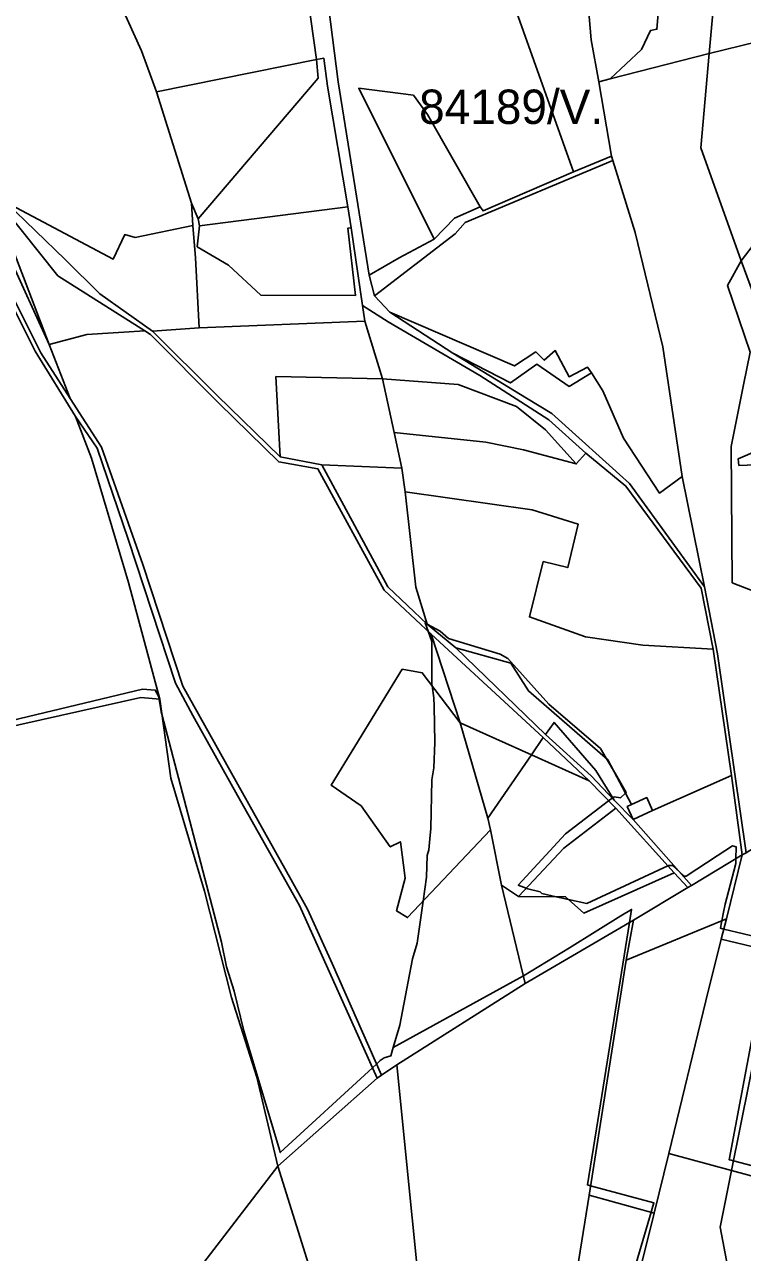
# Model space of a CAD drawing. Extents: x -477304 to -465429, y -1159113 to -1149210.
# Drawn here: x -471269 to -470956, y -1155977 to -1155441 of the extents above; entities that cross this region are included whole.
import ezdxf

# ---------------------------------------------------------------- set-up
doc = ezdxf.new("R2010")
doc.units = 0
for name, color, linetype in [('BPEJ_s', 7, 'Continuous'), ('PUPFL_s', 7, 'Continuous'), ('trav_porost_s', 7, 'Continuous')]:
    doc.layers.add(name, color=color, linetype=linetype)

msp = doc.modelspace()

# ---------------------------------------------------------------- linework, layer by layer
at = {"layer": 'BPEJ_s'}
for points in [[(-470946.75, -1155839.87), (-470963.86, -1155835.82), (-470965.36, -1155835.46), (-470964.99, -1155833.6), (-470964.71, -1155832.16), (-470963.98, -1155828.41), (-470963.32, -1155824.99), (-470961.14, -1155816.67), (-470958.64, -1155807.15), (-470958.58, -1155805.11), (-470958.43, -1155799.92), (-470960.05, -1155799.5), (-470966.71, -1155803.83), (-470980.32, -1155812.67), (-470981.17, -1155812.67), (-470983.22, -1155810.79), (-470986.26, -1155808), (-470987.96, -1155808), (-470988.29, -1155808.15), (-471023.66, -1155824.57), (-471031.62, -1155822.84), (-471037, -1155821.67), (-471043.21, -1155820.32), (-471044.06, -1155819.47), (-471049.37, -1155818.2), (-471050.04, -1155817.95), (-471052.42, -1155817.06), (-471053.59, -1155816.62), (-471033.01, -1155794.19), (-471014.12, -1155779.83), (-471012.54, -1155778.63), (-471012.33, -1155778.47), (-471011.76, -1155778.04), (-471009, -1155778.46), (-471006.75, -1155776.48), (-471006.42, -1155776.18), (-471011.18, -1155768.1), (-471015.21, -1155761.25), (-471017.71, -1155757), (-471040.23, -1155737.67), (-471058.08, -1155717.69), (-471061.48, -1155715.78), (-471084.01, -1155708.98), (-471087.62, -1155705.79), (-471093.25, -1155702.73), (-471093.74, -1155702.47), (-471094.24, -1155702.2), (-471092.9, -1155705.79), (-471091.23, -1155710.26), (-471091.23, -1155728.95), (-471091.13, -1155729.66), (-471090.38, -1155734.9), (-471090.3, -1155738.5), (-471089.95, -1155754.45), (-471090.38, -1155765.5), (-471091.23, -1155770.6), (-471091.66, -1155791.85), (-471092.07, -1155796.37), (-471092.5, -1155801.2), (-471093.35, -1155803.75), (-471093.57, -1155813.1), (-471095.03, -1155823.54), (-471096.31, -1155832.71), (-471097.6, -1155841.99), (-471099.73, -1155848.79), (-471101.63, -1155858.73), (-471105.25, -1155877.69), (-471108.14, -1155887.49), (-471109.22, -1155891.15), (-471112.05, -1155891.93), (-471113.75, -1155893.2), (-471115.36, -1155894.68)], [(-471105.25, -1155877.69), (-471101.63, -1155858.73), (-471099.73, -1155848.79), (-471097.6, -1155841.99), (-471096.31, -1155832.71), (-471095.03, -1155823.54), (-471093.57, -1155813.1), (-471093.35, -1155803.75), (-471092.5, -1155801.2), (-471092.07, -1155796.37), (-471091.66, -1155791.85), (-471091.23, -1155770.6), (-471090.38, -1155765.5), (-471089.95, -1155754.45), (-471090.3, -1155738.5), (-471090.38, -1155734.9), (-471091.13, -1155729.66), (-471091.23, -1155728.95), (-471091.23, -1155710.26), (-471092.9, -1155705.79), (-471094.24, -1155702.2), (-471093.74, -1155702.47), (-471093.25, -1155702.73), (-471087.62, -1155705.79), (-471084.01, -1155708.98), (-471061.48, -1155715.78), (-471058.08, -1155717.69), (-471040.23, -1155737.67), (-471017.71, -1155757), (-471015.21, -1155761.25), (-471011.18, -1155768.1), (-471006.42, -1155776.18), (-471006.75, -1155776.48), (-471009, -1155778.46), (-471011.76, -1155778.04), (-471012.33, -1155778.47), (-471012.54, -1155778.63), (-471014.12, -1155779.83), (-471033.01, -1155794.19), (-471053.59, -1155816.62), (-471052.42, -1155817.06), (-471050.04, -1155817.95), (-471049.37, -1155818.2), (-471044.06, -1155819.47), (-471043.21, -1155820.32), (-471037, -1155821.67), (-471031.62, -1155822.84), (-471023.66, -1155824.57), (-470988.29, -1155808.15), (-470987.96, -1155808), (-470986.26, -1155808), (-470983.22, -1155810.79), (-470981.17, -1155812.67), (-470980.32, -1155812.67), (-470966.71, -1155803.83), (-470960.05, -1155799.5), (-470958.43, -1155799.92), (-470958.58, -1155805.11), (-470958.64, -1155807.15), (-470961.14, -1155816.67), (-470963.32, -1155824.99), (-470963.98, -1155828.41), (-470964.71, -1155832.16), (-470964.99, -1155833.6), (-470965.36, -1155835.46), (-470963.86, -1155835.82), (-470946.75, -1155839.87)], [(-471115.36, -1155894.68), (-471117.11, -1155896.29), (-471157.37, -1155933.32), (-471157.74, -1155932.08), (-471173.25, -1155880.24), (-471177.5, -1155862.82), (-471180.9, -1155852.19), (-471183.02, -1155841.57), (-471209.05, -1155742.05), (-471209.32, -1155741.04), (-471209.37, -1155740.85), (-471210.28, -1155735.41), (-471210.43, -1155734.48), (-471211.92, -1155731.5), (-471217.44, -1155731.08), (-471296.48, -1155749.99)], [(-471117.11, -1155896.29), (-471157.37, -1155933.32), (-471157.74, -1155932.08), (-471173.25, -1155880.24), (-471177.5, -1155862.82), (-471180.9, -1155852.19), (-471183.02, -1155841.57), (-471209.05, -1155742.05), (-471209.32, -1155741.04), (-471209.37, -1155740.85), (-471210.28, -1155735.41), (-471210.43, -1155734.48), (-471211.92, -1155731.5), (-471217.44, -1155731.08), (-471296.48, -1155749.99)], [(-471006.54, -1155996.36), (-470995.6, -1155959.34), (-470995.11, -1155957.69), (-470994.37, -1155955.21), (-471021.99, -1155947.81), (-471023.36, -1155947.44), (-471018.83, -1155919.36), (-471004.98, -1155832.86), (-471004.08, -1155827.23), (-471008.74, -1155830.08), (-471031.12, -1155843.93), (-471051.29, -1155856.17), (-471052.86, -1155857.12), (-471108.14, -1155887.49), (-471109.22, -1155891.15), (-471112.05, -1155891.93), (-471113.75, -1155893.2), (-471115.36, -1155894.68), (-471117.11, -1155896.29)], [(-471006.54, -1155996.36), (-470995.6, -1155959.34), (-470995.11, -1155957.69), (-470994.37, -1155955.21), (-471021.99, -1155947.81), (-471023.36, -1155947.44), (-471018.83, -1155919.36), (-471004.98, -1155832.86), (-471004.08, -1155827.23), (-471008.74, -1155830.08), (-471031.12, -1155843.93), (-471051.29, -1155856.17), (-471052.86, -1155857.12), (-471108.14, -1155887.49), (-471105.25, -1155877.69)], [(-470945.89, -1155853.04), (-470961.58, -1155936.43), (-470960.66, -1155936.68), (-470959.63, -1155936.95), (-470936.97, -1155942.92)], [(-470936.97, -1155942.92), (-470959.63, -1155936.95), (-470960.66, -1155936.68), (-470961.58, -1155936.43), (-470945.89, -1155853.04)]]:
    msp.add_lwpolyline(points, dxfattribs=at)
at = {"layer": 'PUPFL_s'}
for points in [[(-470871.72, -1155069.23), (-470864.73, -1155053.8), (-470854.75, -1155056.73), (-470874.14, -1155116.56), (-470891.69, -1155151.09), (-470909.48, -1155237), (-470913.11, -1155340.83), (-470928.65, -1155443.54), (-470970.24, -1155453.73), (-470967.13, -1155420.04), (-470969.04, -1155388.49), (-470964.39, -1155378.06), (-470961.07, -1155361.45), (-470948.05, -1155328.45), (-470939.67, -1155293.89), (-470930.5, -1155258.99), (-470928.23, -1155233.59), (-470914.76, -1155194.26), (-470902.7, -1155138.01), (-470885.31, -1155112)], [(-471030.7, -1155305.54), (-471026.49, -1155250.14), (-471005.26, -1155255.11), (-470973.9, -1155258.91), (-470971.66, -1155279.02), (-470974.57, -1155299.42), (-470979.84, -1155310.96), (-470979.35, -1155352), (-470985.55, -1155416.23), (-470991.83, -1155427.38), (-470993.06, -1155443.19), (-470995.88, -1155443.78), (-470999.74, -1155451.98), (-471013.47, -1155464.79), (-471018.38, -1155466.05), (-471021.76, -1155447.82), (-471023.89, -1155422.17), (-471027.1, -1155387.89), (-471027.85, -1155373.03), (-471028.89, -1155321.57)], [(-471029.47, -1155505.45), (-471055.82, -1155431.56), (-471023.89, -1155422.17), (-471021.76, -1155447.82), (-471018.38, -1155466.05), (-471012.86, -1155498.59)], [(-470922.05, -1155441.92), (-470912.71, -1155448.67), (-470911.74, -1155457.8), (-470929.64, -1155478.08), (-470940.1, -1155497.88), (-470935.6, -1155508.15), (-470921.58, -1155526.43), (-470937.69, -1155519.96), (-470956.34, -1155544.22), (-470973.93, -1155494.85), (-470970.24, -1155453.73), (-470928.65, -1155443.54)], [(-471136.72, -1155468.07), (-471127.97, -1155520.72), (-471192.67, -1155528.9), (-471193.27, -1155525.88), (-471140.87, -1155464.5), (-471141.59, -1155456.42), (-471138.43, -1155455.84)], [(-471093.14, -1155480.34), (-471070.1, -1155520.72), (-471081.32, -1155525.61), (-471090.19, -1155534.73), (-471123.11, -1155468.9), (-471099.26, -1155472)], [(-471273.7, -1155540.23), (-471258.24, -1155580.74), (-471276.1, -1155541.39), (-471281.34, -1155521.01), (-471292.76, -1155495.07), (-471278.48, -1155520.65)], [(-471118.56, -1155550.53), (-471105.49, -1155542.89), (-471090.19, -1155534.73), (-471081.32, -1155525.61), (-471070.1, -1155520.72), (-471068.89, -1155522.41), (-471029.47, -1155505.45), (-471012.86, -1155498.59), (-471012.35, -1155500.38), (-471076.66, -1155527.49), (-471081.09, -1155532.43), (-471116.28, -1155559.45)], [(-471055.25, -1155590.09), (-471109.58, -1155566.68), (-471116.28, -1155559.45), (-471081.09, -1155532.43), (-471076.66, -1155527.49), (-471012.35, -1155500.38), (-471002.55, -1155531.89), (-470990.4, -1155581.78), (-470982.02, -1155638.32), (-470991.98, -1155645.54), (-471007.57, -1155621.52), (-471016.62, -1155600.94), (-471021.66, -1155593.15), (-471023.34, -1155590.55), (-471031.34, -1155594.82), (-471037.41, -1155583.4), (-471042.22, -1155587.57), (-471045.9, -1155583.93)], [(-471273.7, -1155540.23), (-471278.48, -1155520.65), (-471254.38, -1155550.81), (-471216.42, -1155574.79), (-471241.76, -1155576.36), (-471258.24, -1155580.74)], [(-471225.23, -1155532.73), (-471220.69, -1155534.02), (-471195.51, -1155528.81), (-471194.41, -1155542.94), (-471192.84, -1155573.4), (-471213.1, -1155574.86), (-471236.13, -1155558.57), (-471251.31, -1155543.63), (-471277.2, -1155518.58), (-471230.27, -1155543.46)], [(-471193.27, -1155525.88), (-471192.67, -1155528.9), (-471193.66, -1155538.06), (-471180.04, -1155546.14), (-471165.83, -1155559.17), (-471124.6, -1155559.39), (-471127.87, -1155529.9), (-471126.51, -1155529.78), (-471121.48, -1155563.7), (-471120.46, -1155570.6), (-471192.84, -1155573.4), (-471194.41, -1155542.94), (-471195.51, -1155528.81), (-471196.17, -1155519)], [(-471193.66, -1155538.06), (-471192.67, -1155528.9), (-471127.97, -1155520.72), (-471126.51, -1155529.78), (-471127.87, -1155529.9), (-471124.6, -1155559.39), (-471165.83, -1155559.17), (-471180.04, -1155546.14)], [(-470914.4, -1155607.17), (-470931.76, -1155606.45), (-470931.29, -1155611.8), (-470956.34, -1155544.22), (-470937.69, -1155519.96), (-470921.58, -1155526.43), (-470887.47, -1155552.04), (-470873.85, -1155566.12), (-470857.35, -1155566.55), (-470848.58, -1155576.39), (-470853.43, -1155619.92), (-470854.73, -1155641.51), (-470854.13, -1155654.23), (-470900.02, -1155666.43), (-470911.17, -1155669.39), (-470924.17, -1155632.19), (-470917.24, -1155631.92), (-470917.13, -1155644.81), (-470901.67, -1155639.27), (-470905.37, -1155620.88), (-470890.53, -1155608.96), (-470897.12, -1155598.83)], [(-471282.3, -1155541.4), (-471276.1, -1155541.39), (-471258.24, -1155580.74), (-471249.11, -1155604.34), (-471261.79, -1155584.36), (-471280.71, -1155546.81)], [(-470918.86, -1155705.17), (-470930.94, -1155699.58), (-470935.04, -1155694.42), (-470960.2, -1155684.67), (-470960.68, -1155625.3), (-470955.25, -1155598.32), (-470952.38, -1155584.04), (-470962.2, -1155554.96), (-470956.34, -1155544.22), (-470931.29, -1155611.8), (-470930.28, -1155618.79), (-470957.57, -1155630.57), (-470957.24, -1155633.45), (-470924.17, -1155632.19), (-470911.17, -1155669.39), (-470896.55, -1155699.52)], [(-471040.25, -1155613.59), (-471024.03, -1155628.13), (-471028.27, -1155632.83), (-471041.63, -1155617.95), (-471054.34, -1155607.79), (-471079.79, -1155598.19), (-471112.81, -1155595.72), (-471120.46, -1155570.6), (-471121.48, -1155563.7), (-471110.32, -1155570.83), (-471070.25, -1155594.24)], [(-471042.22, -1155587.57), (-471037.41, -1155583.4), (-471031.34, -1155594.82), (-471023.34, -1155590.55), (-471021.66, -1155593.15), (-471031.41, -1155598.99), (-471045.38, -1155589.34), (-471056.93, -1155597.48), (-471082.09, -1155584.51), (-471109.58, -1155566.68), (-471055.25, -1155590.09), (-471045.9, -1155583.93)], [(-471095.45, -1155723.97), (-471104.15, -1155722.42), (-471135.21, -1155772.95), (-471122.16, -1155782.01), (-471109.4, -1155799.92), (-471104.94, -1155797.69), (-471102.93, -1155813.51), (-471106.63, -1155827.86), (-471101.85, -1155830.74), (-471065.63, -1155792.51), (-471060.91, -1155816.65), (-471050.48, -1155859.52), (-471106.55, -1155894.96), (-471113.25, -1155899.47), (-471134.77, -1155850.77), (-471145.56, -1155827.03), (-471152.68, -1155814.23), (-471199.87, -1155729.83), (-471217.3, -1155676.71), (-471235.38, -1155625.47), (-471249.11, -1155604.34), (-471258.24, -1155580.74), (-471241.76, -1155576.36), (-471216.42, -1155574.79), (-471214.03, -1155576.34), (-471183.98, -1155606.47), (-471158.07, -1155631.94), (-471140.99, -1155635), (-471112.09, -1155687.9), (-471091.56, -1155707.04), (-471078.87, -1155745.79)], [(-471112.81, -1155595.72), (-471159.31, -1155594.74), (-471157.49, -1155629.73), (-471184.9, -1155603), (-471213.1, -1155574.86), (-471192.84, -1155573.4), (-471120.46, -1155570.6)], [(-471007.57, -1155621.52), (-470991.98, -1155645.54), (-470982.02, -1155638.32), (-470972.27, -1155686.51), (-471005.01, -1155641.36), (-471038.88, -1155610.88), (-471049.95, -1155604.08), (-471082.09, -1155584.51), (-471056.93, -1155597.48), (-471045.38, -1155589.34), (-471031.41, -1155598.99), (-471021.66, -1155593.15), (-471016.62, -1155600.94)], [(-471107.72, -1155619.06), (-471104.33, -1155634.63), (-471139.21, -1155633.27), (-471157.49, -1155629.73), (-471159.31, -1155594.74), (-471112.81, -1155595.72)], [(-471112.81, -1155595.72), (-471079.79, -1155598.19), (-471054.34, -1155607.79), (-471041.63, -1155617.95), (-471028.27, -1155632.83), (-471051.2, -1155626.75), (-471067.7, -1155623.28), (-471107.72, -1155619.06)], [(-471246.73, -1155612.1), (-471237.29, -1155625.9), (-471223.81, -1155665.6), (-471203.03, -1155728.5), (-471195.59, -1155742.59), (-471176.08, -1155777.48), (-471148.94, -1155825.52), (-471115.09, -1155900.78), (-471158.43, -1155939.27), (-471167.57, -1155900.46), (-471178.61, -1155865.59), (-471190.45, -1155819.3), (-471205.07, -1155769.96), (-471210, -1155735.43), (-471223.58, -1155684.6), (-471239.68, -1155630.36)], [(-470930.28, -1155618.79), (-470931.29, -1155611.8), (-470924.17, -1155632.19), (-470957.24, -1155633.45), (-470957.57, -1155630.57)], [(-471107.72, -1155619.06), (-471067.7, -1155623.28), (-471051.2, -1155626.75), (-471028.27, -1155632.83), (-471024.03, -1155628.13), (-471006.59, -1155642.47), (-470973.81, -1155687.02), (-470968.56, -1155713.68), (-470999.23, -1155711.96), (-471024.17, -1155708.32), (-471048.65, -1155699.55), (-471042.65, -1155675.45), (-471031.94, -1155678.08), (-471027.48, -1155659.06), (-471047.46, -1155652.8), (-471102.87, -1155645.03), (-471104.33, -1155634.63)], [(-471102.87, -1155645.03), (-471098.21, -1155686.58), (-471093.24, -1155702.75), (-471110.47, -1155686.47), (-471139.21, -1155633.27), (-471104.33, -1155634.63)], [(-471056.8, -1155719.7), (-471080.81, -1155713.1), (-471093.24, -1155702.75), (-471098.21, -1155686.58), (-471102.87, -1155645.03), (-471047.46, -1155652.8), (-471027.48, -1155659.06), (-471031.94, -1155678.08), (-471042.65, -1155675.45), (-471048.65, -1155699.55), (-471024.17, -1155708.32), (-470999.23, -1155711.96), (-470968.56, -1155713.68), (-470960.47, -1155768.78), (-470995.05, -1155784.12), (-470997.46, -1155778.41), (-471004.11, -1155781.47), (-471014.45, -1155761.91), (-471049.14, -1155731.84)], [(-471091.56, -1155707.04), (-471042.61, -1155752.2), (-471047.73, -1155759.71), (-471078.87, -1155745.79)], [(-471005.98, -1155782.33), (-471003.47, -1155787.91), (-471011.67, -1155779.53), (-471019.75, -1155766.55), (-471037.95, -1155745.58), (-471041.66, -1155750.86), (-471080.81, -1155713.1), (-471056.8, -1155719.7), (-471049.14, -1155731.84), (-471014.45, -1155761.91), (-471004.11, -1155781.47)], [(-471078.87, -1155745.79), (-471066.81, -1155787.42), (-471065.63, -1155792.51), (-471101.85, -1155830.74), (-471106.63, -1155827.86), (-471102.93, -1155813.51), (-471104.94, -1155797.69), (-471109.4, -1155799.92), (-471122.16, -1155782.01), (-471135.21, -1155772.95), (-471104.15, -1155722.42), (-471095.45, -1155723.97)], [(-471297.6, -1155752.45), (-471296.48, -1155752.56), (-471280.11, -1155748.53), (-471218.27, -1155734.79), (-471210, -1155735.43), (-471205.07, -1155769.96), (-471190.45, -1155819.3), (-471178.61, -1155865.59), (-471167.57, -1155900.46), (-471158.43, -1155939.27), (-471214.34, -1156011.93), (-471262.2, -1156074.12), (-471263.64, -1156068.5), (-471267.43, -1156054.89), (-471277.02, -1156018.04), (-471286.83, -1155984.06), (-471292.42, -1155939.56), (-471298.69, -1155885.02), (-471302.86, -1155851.34), (-471321.82, -1155797.02), (-471352.28, -1155750.27), (-471327.49, -1155750.42)], [(-471066.81, -1155787.42), (-471078.87, -1155745.79), (-471047.73, -1155759.71)], [(-471041.66, -1155750.86), (-471037.95, -1155745.58), (-471019.75, -1155766.55), (-471011.67, -1155779.53), (-471021.78, -1155768.98)], [(-471047.73, -1155759.71), (-471042.61, -1155752.2), (-471022.59, -1155771.15)], [(-470941.25, -1155845.88), (-470964.96, -1155840.24), (-470962.75, -1155831.35), (-470955.79, -1155803.44), (-470954.15, -1155802.46), (-470867.12, -1155747.52), (-470882.8, -1155793.78), (-470904.43, -1155857.17), (-470935.75, -1155947.84), (-470960.48, -1155941.14)], [(-471053.45, -1155821.59), (-471060.91, -1155816.65), (-471065.63, -1155792.51), (-471066.81, -1155787.42), (-471047.73, -1155759.71), (-471022.59, -1155771.15), (-471010.95, -1155783.08), (-471033.7, -1155800.52)], [(-470955.79, -1155803.44), (-470977.97, -1155816.72), (-471003.47, -1155787.91), (-470995.05, -1155784.12), (-470960.47, -1155768.78)], [(-471004.11, -1155781.47), (-470997.46, -1155778.41), (-470995.05, -1155784.12), (-471003.47, -1155787.91), (-471005.98, -1155782.33)], [(-471032.91, -1155821.69), (-471053.45, -1155821.59), (-471033.7, -1155800.52), (-471010.95, -1155783.08), (-470985.54, -1155811.19), (-471024.87, -1155828.84)], [(-470979.51, -1155817.64), (-470977.97, -1155816.72), (-470955.79, -1155803.44), (-470962.75, -1155831.35), (-471006.43, -1155849.41), (-471003.33, -1155831.89)], [(-470985.54, -1155811.19), (-470979.51, -1155817.64), (-471003.33, -1155831.89), (-471050.48, -1155859.52), (-471060.91, -1155816.65), (-471053.45, -1155821.59), (-471032.91, -1155821.69), (-471024.87, -1155828.84)], [(-470829.99, -1156693.11), (-470839.78, -1156738.1), (-470857.31, -1156707.13), (-470883.93, -1156665.4), (-470899.91, -1156638.59), (-470923.9, -1156598.35), (-470951.29, -1156542.46), (-470998.67, -1156404.46), (-471041.13, -1156278.75), (-471078.8, -1156170.55), (-471091.08, -1156048.56), (-471099.82, -1155961.8), (-471106.55, -1155894.96), (-471050.48, -1155859.52), (-471003.33, -1155831.89), (-471006.43, -1155849.41), (-471022.64, -1155951.92), (-471037.55, -1156045.07), (-471057.43, -1156169.23), (-471005.98, -1156295.75), (-470958.75, -1156412.58), (-470890.49, -1156579.75)], [(-470987.81, -1155933.73), (-470994.28, -1155959.7), (-471022.64, -1155951.92), (-471006.43, -1155849.41), (-470962.75, -1155831.35), (-470964.96, -1155840.24), (-470971.67, -1155867.14)], [(-470971.67, -1155867.14), (-470964.96, -1155840.24), (-470941.25, -1155845.88), (-470960.48, -1155941.14), (-470987.81, -1155933.73)], [(-470899.91, -1156638.59), (-470911.91, -1156646.55), (-470951.05, -1156583.4), (-470968.09, -1156553.33), (-470971.14, -1156547.88), (-470975.38, -1156532.59), (-471011.57, -1156415.99), (-471061.89, -1156254.93), (-471094.26, -1156148.89), (-471118.52, -1156067.04), (-471158.43, -1155939.27), (-471115.09, -1155900.78), (-471113.25, -1155899.47), (-471106.55, -1155894.96), (-471099.82, -1155961.8), (-471091.08, -1156048.56), (-471078.8, -1156170.55), (-471041.13, -1156278.75), (-470998.67, -1156404.46), (-470951.29, -1156542.46), (-470923.9, -1156598.35)], [(-470965.47, -1155965.84), (-470959.29, -1155997.99), (-470993.51, -1156097.54), (-471010.25, -1156167.48), (-471046.02, -1156169.04), (-471016.4, -1156048.46), (-470994.28, -1155959.7), (-470987.81, -1155933.73), (-470960.48, -1155941.14)], [(-471218.65, -1156131.76), (-471256.12, -1156096.18), (-471262.2, -1156074.12), (-471214.34, -1156011.93), (-471158.43, -1155939.27), (-471118.52, -1156067.04), (-471168.99, -1156077.91), (-471153.56, -1156131.85)], [(-470935.75, -1155947.84), (-470955.14, -1156006.49), (-471010.25, -1156167.48), (-470993.51, -1156097.54), (-470959.29, -1155997.99), (-470965.47, -1155965.84), (-470960.48, -1155941.14)], [(-471016.4, -1156048.46), (-471046.02, -1156169.04), (-470993.12, -1156290.52), (-470943.01, -1156405.58), (-470908.05, -1156482.93), (-470882.28, -1156541.77), (-470842.07, -1156630.77), (-470824.8, -1156668), (-470829.99, -1156693.11), (-470890.49, -1156579.75), (-470958.75, -1156412.58), (-471005.98, -1156295.75), (-471057.43, -1156169.23), (-471037.55, -1156045.07), (-471022.64, -1155951.92), (-470994.28, -1155959.7)]]:
    msp.add_lwpolyline(points, close=True, dxfattribs=at)
for points in [[(-470967.13, -1155420.04), (-470970.24, -1155453.73), (-471013.47, -1155464.79), (-470999.74, -1155451.98), (-470995.88, -1155443.78), (-470993.06, -1155443.19), (-470991.83, -1155427.38)], [(-471055.82, -1155431.56), (-471029.47, -1155505.45), (-471068.89, -1155522.41), (-471070.1, -1155520.72), (-471093.14, -1155480.34), (-471099.26, -1155472), (-471123.11, -1155468.9), (-471090.19, -1155534.73), (-471105.49, -1155542.89), (-471118.56, -1155550.53), (-471132.12, -1155466.08), (-471137.12, -1155427.35)], [(-470954.15, -1155802.46), (-470966.6, -1155715.68), (-470972.27, -1155686.51), (-470982.02, -1155638.32), (-470990.4, -1155581.78), (-471002.55, -1155531.89), (-471012.35, -1155500.38), (-471012.86, -1155498.59), (-471018.38, -1155466.05), (-471013.47, -1155464.79), (-470970.24, -1155453.73), (-470973.93, -1155494.85), (-470956.34, -1155544.22), (-470962.2, -1155554.96), (-470952.38, -1155584.04)], [(-471286.26, -1155540.01), (-471264.38, -1155583.69), (-471246.73, -1155612.1), (-471239.68, -1155630.36), (-471223.58, -1155684.6), (-471210, -1155735.43), (-471218.27, -1155734.79), (-471280.11, -1155748.53)], [(-470955.25, -1155598.32), (-470960.68, -1155625.3), (-470960.2, -1155684.67), (-470935.04, -1155694.42)]]:
    msp.add_lwpolyline(points, dxfattribs=at)
at = {"layer": 'trav_porost_s'}
for points in [[(-471298.37, -1155182.35), (-471246.67, -1155218.25), (-471212.72, -1155248.03), (-471199.18, -1155263.13), (-471169.91, -1155284.6), (-471158.71, -1155297.16), (-471144.07, -1155323.2), (-471139.25, -1155338.96), (-471142.7, -1155405.79), (-471145.29, -1155429.25), (-471141.59, -1155456.42), (-471211.42, -1155470.43), (-471217.87, -1155452.64), (-471240.71, -1155401.92), (-471257.39, -1155368.39), (-471263.78, -1155360.73), (-471275.82, -1155346.29)], [(-471277.47, -1155347.6), (-471265.84, -1155362.47), (-471263.78, -1155360.73), (-471257.39, -1155368.39), (-471240.71, -1155401.92), (-471217.87, -1155452.64), (-471211.42, -1155470.43), (-471196.17, -1155519), (-471195.51, -1155528.81), (-471220.69, -1155534.02), (-471225.23, -1155532.73), (-471230.27, -1155543.46), (-471277.2, -1155518.58)]]:
    msp.add_lwpolyline(points, dxfattribs=at)
msp.add_lwpolyline([(-471141.59, -1155456.42), (-471140.87, -1155464.5), (-471193.27, -1155525.88), (-471196.17, -1155519), (-471211.42, -1155470.43)], close=True, dxfattribs=at)

# ---------------------------------------------------------------- texts
at = {"layer": 'BPEJ_s'}
msp.add_text('84189/V.', height=15, dxfattribs=at).set_placement((-471096.82, -1155484.5))

doc.saveas('drawing.dxf')
